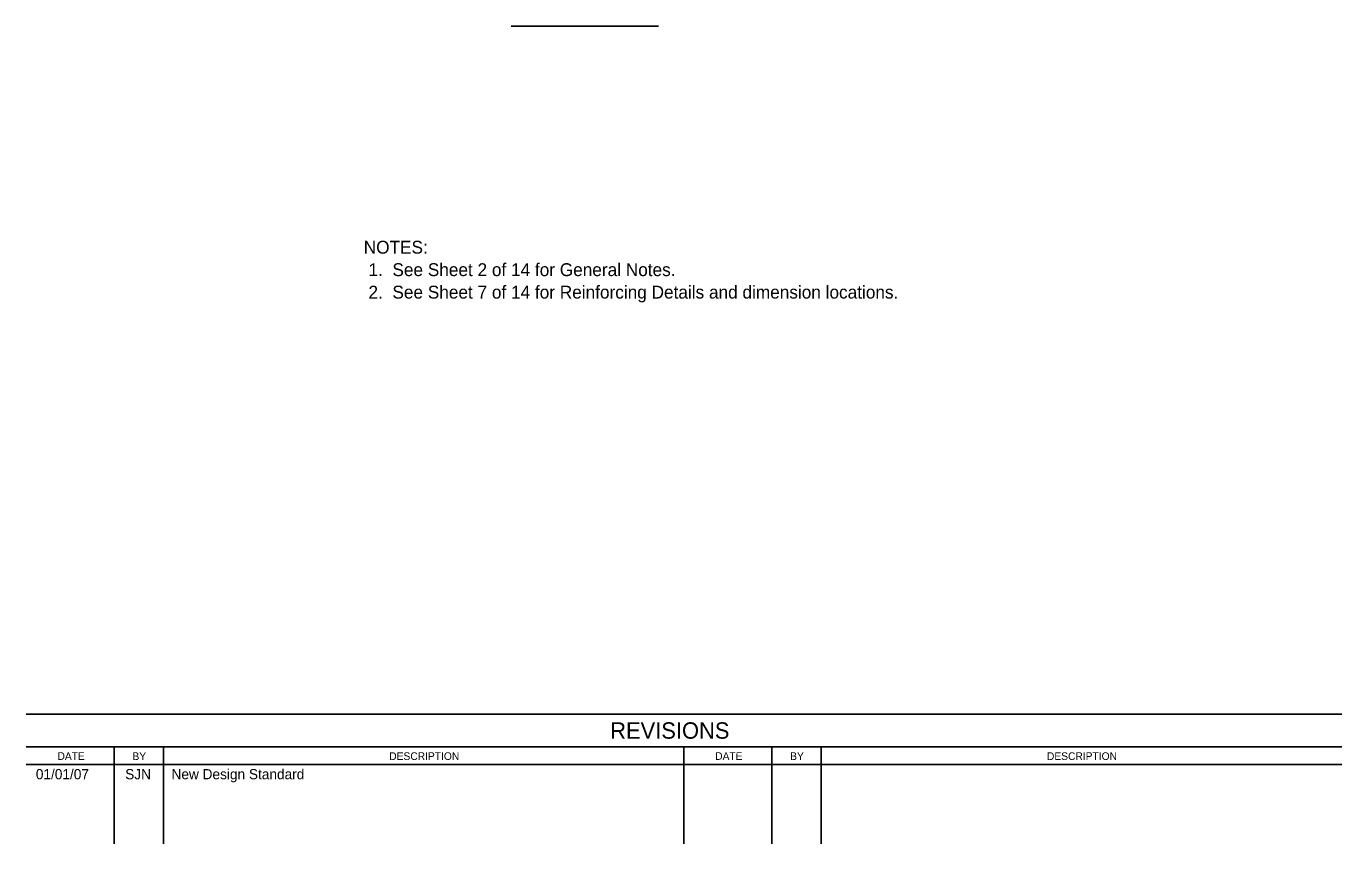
# Model space of a CAD drawing. Extents: x 10340.6 to 10376, y 76398.7 to 76415.8.
# Drawn here: x 10340.62 to 10350.93, y 76398.72 to 76405.12 of the extents above; entities that cross this region are included whole.
import ezdxf

# ---------------------------------------------------------------- set-up
doc = ezdxf.new("R2010")
doc.units = 0
for name, color, linetype in [('AdhocPoint_dp', 7, 'Continuous'), ('Border', 7, 'Continuous'), ('PlotBorder_dp', 7, 'Continuous')]:
    doc.layers.add(name, color=color, linetype=linetype)

msp = doc.modelspace()

# ---------------------------------------------------------------- linework, layer by layer
at = {"layer": 'Border'}
for p, q in [((10350.927, 76399.73), (10340.621, 76399.73)), ((10350.927, 76399.473), (10340.621, 76399.473)), ((10341.31, 76399.473), (10341.31, 76398.715)), ((10341.696, 76399.473), (10341.696, 76398.715)), ((10345.774, 76399.473), (10345.774, 76398.715)), ((10346.463, 76399.473), (10346.463, 76398.715)), ((10346.849, 76399.473), (10346.849, 76398.715)), ((10340.621, 76399.336), (10350.927, 76399.336))]:
    msp.add_line(p, q, dxfattribs=at)
at = {"layer": 'PlotBorder_dp'}
msp.add_line((10344.419, 76405.121), (10345.574, 76405.121), dxfattribs=at)
msp.add_line((10344.419, 76405.121), (10345.574, 76405.121), dxfattribs=at)
msp.add_line((10344.419, 76405.121), (10345.574, 76405.121), dxfattribs=at)

# ---------------------------------------------------------------- texts
at = {"layer": 'AdhocPoint_dp'}
for s, height, p in [('REVISIONS', 0.1283, (10345.196, 76399.538)), ('BY', 0.0601, (10341.453, 76399.371)), ('BY', 0.0601, (10346.606, 76399.371)), ('01/01/07', 0.08, (10340.696, 76399.22)), ('SJN', 0.08, (10341.396, 76399.22)), ('New Design Standard', 0.08, (10341.759, 76399.22))]:
    msp.add_text(s, height=height, dxfattribs=at).set_placement(p)
for s, height, rotation, p in [('DATE', 0.0598, 359.8693, (10340.866, 76399.372)), ('DESCRIPTION', 0.06003, 0.0498, (10343.465, 76399.371)), ('DATE', 0.0598, 359.8693, (10346.019, 76399.372)), ('DESCRIPTION', 0.06003, 0.0498, (10348.618, 76399.371))]:
    msp.add_text(s, height=height, rotation=rotation, dxfattribs=at).set_placement(p)
at = {"layer": 'PlotBorder_dp'}
for s, p in [('NOTES:', (10343.265, 76403.339)), (' 1.  See Sheet 2 of 14 for General Notes.', (10343.265, 76403.163)), (' 2.  See Sheet 7 of 14 for Reinforcing Details and dimension locations.', (10343.265, 76402.987))]:
    msp.add_text(s, height=0.1008, dxfattribs=at).set_placement(p)

doc.saveas('drawing.dxf')
